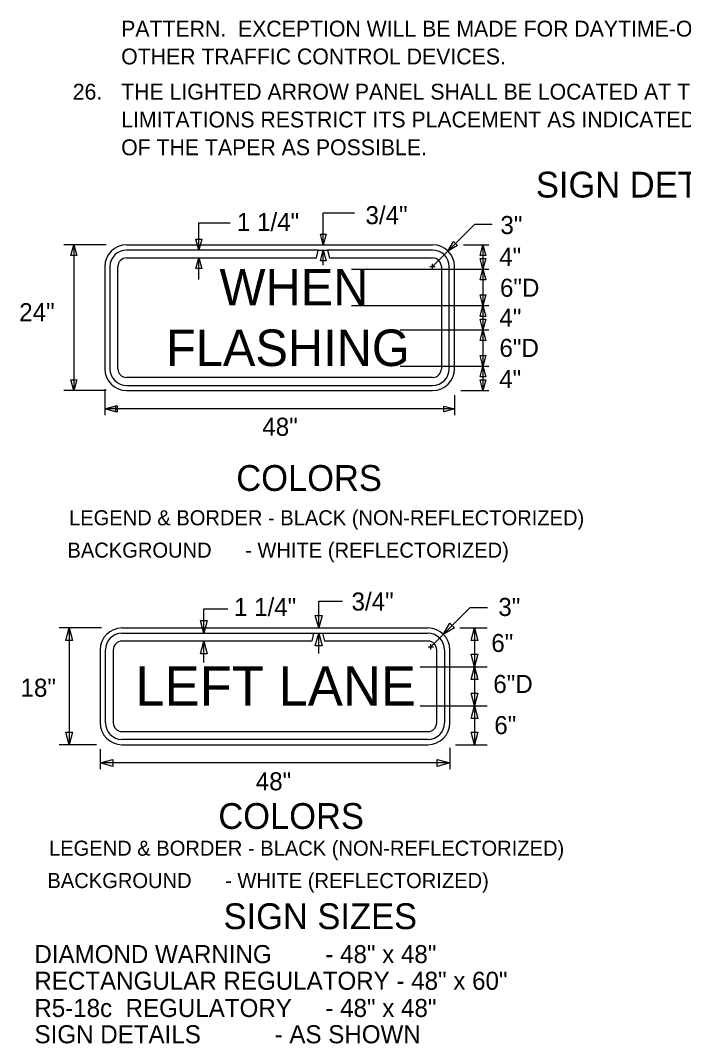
# Model space of a CAD drawing. Extents: x 15277 to 18126, y 1908 to 6555.
# Drawn here: x 17436.4 to 17744.9, y 2193.3 to 2669.2 of the extents above; entities that cross this region are included whole.
import ezdxf

# ---------------------------------------------------------------- set-up
doc = ezdxf.new("R2010")
doc.units = 0
for name, color, linetype in [('MT_SCRATCH_LEVEL_A', 7, 'Continuous'), ('TYPICAL_EX', 7, 'Continuous'), ('TYPICAL_TEXT_DIMEN_EX', 7, 'Continuous'), ('TYPICAL_TEXT_DIMEN_PR', 7, 'Continuous')]:
    doc.layers.add(name, color=color, linetype=linetype)

msp = doc.modelspace()

# ---------------------------------------------------------------- linework, layer by layer
at = {"layer": 'MT_SCRATCH_LEVEL_A'}
for p, q in [((17577.3, 2579.66), (17591.85, 2579.66)), ((17519.35, 2575.12), (17533.9, 2575.12)), ((17635.31, 2561.91), (17647.66, 2574.32)), ((17655.86, 2574.32), (17647.66, 2574.32)), ((17628.16, 2554.73), (17635.31, 2561.91)), ((17628.16, 2553.51), (17628.16, 2556.01)), ((17626.91, 2554.73), (17629.41, 2554.73)), ((17475.57, 2497.7), (17475.57, 2485.62)), ((17638.33, 2494.97), (17638.33, 2485.62)), ((17638.33, 2488.53), (17475.57, 2488.53)), ((17575.14, 2399.05), (17586.28, 2399.05)), ((17521.69, 2395.58), (17532.82, 2395.58)), ((17633.15, 2383.67), (17645.48, 2396.05)), ((17653.65, 2396.05), (17645.48, 2396.05)), ((17627.35, 2377.85), (17633.15, 2383.67)), ((17626.06, 2377.85), (17628.6, 2377.85)), ((17627.35, 2376.63), (17627.35, 2379.11)), ((17473.44, 2330.34), (17473.44, 2320.93)), ((17636.16, 2330.92), (17636.16, 2320.93)), ((17636.16, 2323.85), (17473.44, 2323.85))]:
    msp.add_line(p, q, dxfattribs=at)
at = {"layer": 'TYPICAL_EX'}
for p, q in [((17485.74, 2564.87), (17628.16, 2564.87)), ((17574.89, 2562.43), (17485.74, 2562.43)), ((17574.07, 2558.77), (17574.89, 2562.43)), ((17574.89, 2562.43), (17579.3, 2562.43)), ((17628.16, 2562.43), (17579.3, 2562.43)), ((17579.3, 2562.43), (17580.24, 2558.77)), ((17485.74, 2558.77), (17574.07, 2558.77)), ((17580.24, 2558.77), (17628.16, 2558.77)), ((17475.57, 2554.7), (17475.57, 2507.22)), ((17478.01, 2554.7), (17478.01, 2507.22)), ((17481.67, 2507.22), (17481.67, 2554.7)), ((17632.23, 2554.7), (17632.23, 2507.22)), ((17635.89, 2507.22), (17635.89, 2554.7)), ((17638.33, 2507.22), (17638.33, 2554.7)), ((17628.16, 2503.15), (17485.74, 2503.15)), ((17485.74, 2499.49), (17628.16, 2499.49)), ((17485.74, 2497.04), (17628.16, 2497.04)), ((17483.61, 2386.63), (17625.99, 2386.63)), ((17483.61, 2384.19), (17572.73, 2384.19)), ((17572.73, 2384.19), (17571.92, 2380.53)), ((17572.73, 2384.19), (17577.14, 2384.19)), ((17571.92, 2380.53), (17483.61, 2380.53)), ((17473.44, 2376.46), (17473.44, 2342.53)), ((17475.88, 2342.53), (17475.88, 2376.46)), ((17479.54, 2376.46), (17479.54, 2342.53)), ((17636.16, 2342.53), (17636.16, 2376.46)), ((17483.61, 2338.46), (17625.99, 2338.46)), ((17625.99, 2334.8), (17483.61, 2334.8)), ((17483.61, 2332.36), (17625.99, 2332.36))]:
    msp.add_line(p, q, dxfattribs=at)
for centre, radius, start, end in [((17485.74, 2554.7), 10.17, 90, 180), ((17485.74, 2554.7), 7.73, 90, 180), ((17628.16, 2554.7), 10.17, 0, 90), ((17628.16, 2554.7), 7.73, 0, 90), ((17485.74, 2554.7), 4.07, 90, 180), ((17628.16, 2554.7), 4.07, 0, 90), ((17485.74, 2507.21), 10.17, 180, 270), ((17485.74, 2507.21), 7.73, 180, 270), ((17485.74, 2507.21), 4.07, 180, 270), ((17628.16, 2507.21), 10.17, 270, 0), ((17628.16, 2507.21), 4.07, 270, 0), ((17628.16, 2507.21), 7.73, 270, 0), ((17483.61, 2376.46), 10.17, 90, 180), ((17483.61, 2376.46), 7.73, 90, 180), ((17625.99, 2376.46), 10.17, 0, 90), ((17483.61, 2376.46), 4.07, 90, 180), ((17483.61, 2342.53), 10.17, 180, 270), ((17483.61, 2342.53), 7.73, 180, 270), ((17483.61, 2342.53), 4.07, 180, 270), ((17625.99, 2342.53), 10.17, 270, 0), ((17625.99, 2342.53), 7.73, 270, 0), ((17625.99, 2342.53), 4.07, 270, 0)]:
    msp.add_arc(centre, radius, start, end, dxfattribs=at)
at = {"layer": 'TYPICAL_TEXT_DIMEN_PR'}
for p, q in [((17577.3, 2564.87), (17577.3, 2579.66)), ((17519.35, 2562.43), (17519.35, 2575.12)), ((17577.3, 2564.87), (17575.96, 2569.85)), ((17575.96, 2569.85), (17577.3, 2569.85)), ((17577.3, 2569.85), (17578.63, 2569.85)), ((17578.63, 2569.85), (17577.3, 2564.87)), ((17519.35, 2562.43), (17518.02, 2567.41)), ((17518.02, 2567.41), (17519.35, 2567.41)), ((17519.35, 2567.41), (17520.69, 2567.41)), ((17520.69, 2567.41), (17519.35, 2562.43)), ((17635.31, 2561.91), (17637.88, 2566.39)), ((17637.88, 2566.39), (17638.82, 2565.45)), ((17638.82, 2565.45), (17639.77, 2564.5)), ((17476.23, 2564.87), (17456.48, 2564.87)), ((17459.87, 2559.89), (17461.2, 2564.87)), ((17461.2, 2564.87), (17461.2, 2497.04)), ((17461.2, 2564.87), (17462.54, 2559.89)), ((17575.96, 2557.45), (17577.3, 2562.43)), ((17577.3, 2555.4), (17577.3, 2562.43)), ((17577.3, 2562.43), (17578.63, 2557.45)), ((17639.77, 2564.5), (17635.31, 2561.91)), ((17642.6, 2564.87), (17654.29, 2564.87)), ((17650.26, 2559.89), (17651.59, 2564.87)), ((17651.59, 2564.87), (17651.59, 2553.55)), ((17651.59, 2564.87), (17652.92, 2559.89)), ((17461.2, 2559.89), (17459.87, 2559.89)), ((17462.54, 2559.89), (17461.2, 2559.89)), ((17518.02, 2553.78), (17519.35, 2558.77)), ((17519.35, 2548.68), (17519.35, 2558.77)), ((17519.35, 2558.77), (17520.69, 2553.78)), ((17577.3, 2557.45), (17575.96, 2557.45)), ((17578.63, 2557.45), (17577.3, 2557.45)), ((17651.59, 2559.89), (17650.26, 2559.89)), ((17651.59, 2553.55), (17650.26, 2558.53)), ((17650.26, 2558.53), (17651.59, 2558.53)), ((17652.92, 2559.89), (17651.59, 2559.89)), ((17651.59, 2558.53), (17652.92, 2558.53)), ((17652.92, 2558.53), (17651.59, 2553.55)), ((17519.35, 2553.78), (17518.02, 2553.78)), ((17520.69, 2553.78), (17519.35, 2553.78)), ((17590.39, 2553.55), (17654.29, 2553.55)), ((17650.26, 2548.57), (17651.59, 2553.55)), ((17651.59, 2553.55), (17651.59, 2536.57)), ((17651.59, 2553.55), (17652.92, 2548.57)), ((17651.59, 2548.57), (17650.26, 2548.57)), ((17652.92, 2548.57), (17651.59, 2548.57)), ((17651.59, 2536.57), (17650.26, 2541.55)), ((17650.26, 2541.55), (17651.59, 2541.55)), ((17651.59, 2541.55), (17652.92, 2541.55)), ((17652.92, 2541.55), (17651.59, 2536.57)), ((17590.39, 2536.57), (17654.29, 2536.57)), ((17650.26, 2531.59), (17651.59, 2536.57)), ((17651.59, 2536.57), (17651.59, 2525.34)), ((17651.59, 2536.57), (17652.92, 2531.59)), ((17651.59, 2531.59), (17650.26, 2531.59)), ((17651.59, 2525.34), (17650.26, 2530.33)), ((17650.26, 2530.33), (17651.59, 2530.33)), ((17651.59, 2525.34), (17650.26, 2530.33)), ((17650.26, 2530.33), (17651.59, 2530.33)), ((17652.92, 2531.59), (17651.59, 2531.59)), ((17651.59, 2530.33), (17652.92, 2530.33)), ((17652.92, 2530.33), (17651.59, 2525.34)), ((17651.59, 2530.33), (17652.92, 2530.33)), ((17652.92, 2530.33), (17651.59, 2525.34)), ((17612.99, 2525.34), (17654.29, 2525.34)), ((17650.26, 2520.36), (17651.59, 2525.34)), ((17651.59, 2525.34), (17651.59, 2508.36)), ((17651.59, 2525.34), (17652.92, 2520.36)), ((17651.59, 2520.36), (17650.26, 2520.36)), ((17652.92, 2520.36), (17651.59, 2520.36)), ((17651.59, 2508.36), (17650.26, 2513.35)), ((17650.26, 2513.35), (17651.59, 2513.35)), ((17651.59, 2508.36), (17650.26, 2513.35)), ((17650.26, 2513.35), (17651.59, 2513.35)), ((17651.59, 2513.35), (17652.92, 2513.35)), ((17652.92, 2513.35), (17651.59, 2508.36)), ((17651.59, 2513.35), (17652.92, 2513.35)), ((17652.92, 2513.35), (17651.59, 2508.36)), ((17612.99, 2508.36), (17654.29, 2508.36)), ((17650.26, 2503.38), (17651.59, 2508.36)), ((17651.59, 2508.36), (17651.59, 2497.04)), ((17651.59, 2508.36), (17652.92, 2503.38)), ((17651.59, 2503.38), (17650.26, 2503.38)), ((17652.92, 2503.38), (17651.59, 2503.38)), ((17461.2, 2497.04), (17459.87, 2502.03)), ((17459.87, 2502.03), (17461.2, 2502.03)), ((17461.2, 2502.03), (17462.54, 2502.03)), ((17462.54, 2502.03), (17461.2, 2497.04)), ((17651.59, 2497.04), (17650.26, 2502.03)), ((17650.26, 2502.03), (17651.59, 2502.03)), ((17651.59, 2502.03), (17652.92, 2502.03)), ((17652.92, 2502.03), (17651.59, 2497.04)), ((17476.23, 2497.04), (17456.48, 2497.04)), ((17641.35, 2497.04), (17654.29, 2497.04)), ((17475.57, 2488.53), (17481.43, 2490.1)), ((17475.57, 2488.53), (17480.55, 2489.87)), ((17480.55, 2489.87), (17480.55, 2488.53)), ((17481.43, 2490.1), (17481.43, 2488.53)), ((17633.35, 2488.53), (17633.35, 2489.87)), ((17633.35, 2489.87), (17638.33, 2488.53)), ((17481.43, 2486.96), (17475.57, 2488.53)), ((17480.55, 2487.2), (17475.57, 2488.53)), ((17480.55, 2488.53), (17480.55, 2487.2)), ((17481.43, 2488.53), (17481.43, 2486.96)), ((17638.33, 2488.53), (17633.35, 2487.2)), ((17633.35, 2487.2), (17633.35, 2488.53)), ((17575.14, 2386.63), (17575.14, 2399.05)), ((17521.69, 2384.19), (17521.69, 2395.58)), ((17521.69, 2384.19), (17520.12, 2390.05)), ((17520.12, 2390.05), (17521.69, 2390.05)), ((17521.69, 2390.05), (17523.26, 2390.05)), ((17523.26, 2390.05), (17521.69, 2384.19)), ((17575.14, 2386.63), (17573.57, 2392.49)), ((17573.57, 2392.49), (17575.14, 2392.49)), ((17575.14, 2392.49), (17576.71, 2392.49)), ((17576.71, 2392.49), (17575.14, 2386.63)), ((17633.15, 2383.67), (17636.17, 2388.93)), ((17636.17, 2388.93), (17637.28, 2387.83)), ((17474.08, 2386.63), (17454.36, 2386.63)), ((17457.5, 2380.77), (17459.07, 2386.63)), ((17459.07, 2386.63), (17459.07, 2332.36)), ((17459.07, 2386.63), (17460.64, 2380.77)), ((17483.61, 2384.19), (17572.73, 2384.19)), ((17572.73, 2384.19), (17571.92, 2380.53)), ((17573.57, 2378.33), (17575.14, 2384.19)), ((17575.14, 2374.83), (17575.14, 2384.19)), ((17575.14, 2384.19), (17576.71, 2378.33)), ((17578.06, 2380.53), (17577.14, 2384.19)), ((17577.14, 2384.19), (17625.99, 2384.19)), ((17638.4, 2386.72), (17633.15, 2383.67)), ((17637.28, 2387.83), (17638.4, 2386.72)), ((17640.78, 2386.63), (17653.49, 2386.63)), ((17646.12, 2380.77), (17647.69, 2386.63)), ((17647.69, 2386.63), (17647.69, 2368.54)), ((17647.69, 2386.63), (17649.26, 2380.77)), ((17459.07, 2380.77), (17457.5, 2380.77)), ((17460.64, 2380.77), (17459.07, 2380.77)), ((17571.92, 2380.53), (17483.61, 2380.53)), ((17520.12, 2374.67), (17521.69, 2380.53)), ((17521.69, 2370.54), (17521.69, 2380.53)), ((17521.69, 2380.53), (17523.26, 2374.67)), ((17625.99, 2380.53), (17578.06, 2380.53)), ((17647.69, 2380.77), (17646.12, 2380.77)), ((17649.26, 2380.77), (17647.69, 2380.77)), ((17475.88, 2342.53), (17475.88, 2376.46)), ((17479.54, 2376.46), (17479.54, 2342.53)), ((17521.69, 2374.67), (17520.12, 2374.67)), ((17523.26, 2374.67), (17521.69, 2374.67)), ((17575.14, 2378.33), (17573.57, 2378.33)), ((17576.71, 2378.33), (17575.14, 2378.33)), ((17630.06, 2342.53), (17630.06, 2376.46)), ((17633.72, 2376.46), (17633.72, 2342.53)), ((17647.69, 2368.54), (17646.12, 2374.4)), ((17646.12, 2374.4), (17647.69, 2374.4)), ((17647.69, 2374.4), (17649.26, 2374.4)), ((17649.26, 2374.4), (17647.69, 2368.54)), ((17622.35, 2368.54), (17653.49, 2368.54)), ((17646.12, 2362.68), (17647.69, 2368.54)), ((17647.69, 2368.54), (17647.69, 2350.45)), ((17647.69, 2368.54), (17649.26, 2362.68)), ((17647.69, 2362.68), (17646.12, 2362.68)), ((17649.26, 2362.68), (17647.69, 2362.68)), ((17647.69, 2350.45), (17646.12, 2356.31)), ((17646.12, 2356.31), (17647.69, 2356.31)), ((17647.69, 2356.31), (17649.26, 2356.31)), ((17649.26, 2356.31), (17647.69, 2350.45)), ((17622.35, 2350.45), (17653.49, 2350.45)), ((17646.12, 2344.59), (17647.69, 2350.45)), ((17647.69, 2350.45), (17647.69, 2332.36)), ((17647.69, 2350.45), (17649.26, 2344.59)), ((17647.69, 2344.59), (17646.12, 2344.59)), ((17649.26, 2344.59), (17647.69, 2344.59)), ((17459.07, 2332.36), (17457.5, 2338.22)), ((17457.5, 2338.22), (17459.07, 2338.22)), ((17459.07, 2338.22), (17460.64, 2338.22)), ((17460.64, 2338.22), (17459.07, 2332.36)), ((17483.61, 2338.46), (17625.99, 2338.46)), ((17647.69, 2332.36), (17646.12, 2338.22)), ((17646.12, 2338.22), (17647.69, 2338.22)), ((17647.69, 2338.22), (17649.26, 2338.22)), ((17649.26, 2338.22), (17647.69, 2332.36)), ((17471.81, 2332.36), (17454.36, 2332.36)), ((17625.99, 2334.8), (17483.61, 2334.8)), ((17638.78, 2332.36), (17653.49, 2332.36)), ((17473.44, 2323.85), (17479.3, 2325.42)), ((17479.3, 2322.28), (17473.44, 2323.85)), ((17479.3, 2325.42), (17479.3, 2323.85)), ((17479.3, 2323.85), (17479.3, 2322.28)), ((17630.3, 2323.85), (17630.3, 2325.42)), ((17630.3, 2325.42), (17636.16, 2323.85)), ((17636.16, 2323.85), (17630.3, 2322.28)), ((17630.3, 2322.28), (17630.3, 2323.85))]:
    msp.add_line(p, q, dxfattribs=at)
for centre, radius, start, end in [((17483.61, 2376.46), 7.73, 90, 180), ((17625.99, 2376.46), 7.73, 0, 90), ((17483.61, 2376.46), 4.07, 90, 180), ((17625.99, 2376.46), 4.07, 0, 90), ((17483.61, 2342.53), 7.73, 180, 270), ((17483.61, 2342.53), 4.07, 180, 270), ((17625.99, 2342.53), 4.07, 270, 0), ((17625.99, 2342.53), 7.73, 270, 0)]:
    msp.add_arc(centre, radius, start, end, dxfattribs=at)

# ---------------------------------------------------------------- texts
at = {"layer": 'TYPICAL_TEXT_DIMEN_EX'}
for s, height, p in [('WHEN   ', 16.968, (17528.99, 2536.66)), ('FLASHING', 16.968, (17504.08, 2508.48)), ('LEFT LANE', 18.308, (17489.8, 2350.51))]:
    msp.add_text(s, height=height, dxfattribs=at).set_placement(p)
at = {"layer": 'TYPICAL_TEXT_DIMEN_PR'}
for s, height, p in [('PATTERN.  EXCEPTION WILL BE MADE FOR DAYTIME-ONLY TRAFFIC PATTERNS THAT ARE ADEQUATELY DELINEATED BY', 7.392, (17483.23, 2661.71)), ('OTHER TRAFFIC CONTROL DEVICES.', 7.392, (17483.23, 2648.78)), ('26.', 7.392, (17460.69, 2632.39)), ('THE LIGHTED ARROW PANEL SHALL BE LOCATED AT THE BEGINNING OF THE TAPER AS SHOWN.  WHEN PHYSICAL', 7.392, (17483.23, 2632.39)), ('LIMITATIONS RESTRICT ITS PLACEMENT AS INDICATED, THEN IT SHALL BE PLACED AS CLOSE TO THE BEGINNING', 7.392, (17483.23, 2619.45)), ('OF THE TAPER AS POSSIBLE.', 7.392, (17483.23, 2606.52)), ('SIGN DETAILS', 12, (17676.24, 2586.85)), ('1 1/4"', 8.4, (17537.08, 2571.3)), ('3/4"', 8.4, (17596.93, 2574.44)), ('3"', 8.4, (17659.72, 2569.85)), ('4"', 8.4, (17659.16, 2555.08)), ('6"D', 8.4, (17659.51, 2540.69)), ('24"', 8.4, (17435.79, 2529.32)), ('4"', 8.4, (17659.25, 2526.82)), ('6"D', 8.4, (17659.28, 2512.72)), ('4"', 8.4, (17659.16, 2498.19)), ('48"', 8.4, (17548.92, 2476.04)), ('COLORS', 12, (17536.8, 2450.4)), ('LEGEND & BORDER - BLACK (NON-REFLECTORIZED)', 7, (17458.96, 2434.4)), ('BACKGROUND      - WHITE (REFLECTORIZED)', 7, (17458.23, 2419.35)), ('3/4"', 8.4, (17590.44, 2394.74)), ('1 1/4"', 8.4, (17535.73, 2392.16)), ('3"', 8.4, (17658.75, 2392.22)), ('6"', 8.4, (17655.48, 2375.47)), ('18"', 8.4, (17436.4, 2354.65)), ('6"D', 8.4, (17656.41, 2356.41)), ('6"', 8.4, (17656.87, 2337.23)), ('48"', 8.4, (17545.87, 2311.12)), ('COLORS', 12, (17528.44, 2293.17)), ('LEGEND & BORDER - BLACK (NON-REFLECTORIZED)', 7, (17449.64, 2280.71)), ('BACKGROUND      - WHITE (REFLECTORIZED)', 7, (17448.91, 2265.66)), ('SIGN SIZES', 12, (17530.86, 2246.56)), ('DIAMOND WARNING        - 48" x 48"', 8.4, (17442.82, 2230.74)), ('RECTANGULAR REGULATORY - 48" x 60"', 8.4, (17442.82, 2218.34)), ('R5-18c  REGULATORY     - 48" x 48"', 8.4, (17442.82, 2205.69)), ('SIGN DETAILS           - AS SHOWN', 8.4, (17442.9, 2193.46))]:
    msp.add_text(s, height=height, dxfattribs=at).set_placement(p)

doc.saveas('drawing.dxf')
